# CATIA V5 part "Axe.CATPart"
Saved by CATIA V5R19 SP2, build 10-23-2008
Part number: Axe
Bounding box of the stored display mesh (mm): x -4.999 to 4.999, y -33.5 to 33.5, z -4.999 to 4.999
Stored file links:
  F:\Projet CAO\pièces et assemblages\mécanisme 558\558-SaintAime\CAO\Axe.CATPart
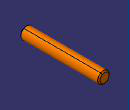
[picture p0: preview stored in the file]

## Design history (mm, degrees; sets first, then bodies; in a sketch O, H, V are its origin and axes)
Body1 (main body)
  Sketch1 on yz-plane, origin (0, 0, 0), H (0, 1, 0), V (0, 0, 1)
    point P1 (-33.5, 0)
    line L1 (-33.5, 0) -> (-33.5, 5)
    line L2 (-33.5, 5) -> (33.5, 5)
    line L3 (33.5, 5) -> (33.5, 0)
    point P4 (33.5, 0)
    line L4 (33.5, 0) -> (-33.5, 0)
    distance L2 L4 = 5
    distance L3 L1 = 67
    coincidence: P1 H, P4 H
    vertical: L1 V, L3 V
    horizontal: L2 H, L4 H
    symmetry: L1 L3 V
  Shaft1: profile Sketch1, axis Sketch1.L4, angle 360
  Chamfer1: length 1, angle 45, on edge [face of Shaft1 from Sketch1.L2 | face of Shaft1 from Sketch1.L3]; face of Shaft1 from Sketch1.L1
